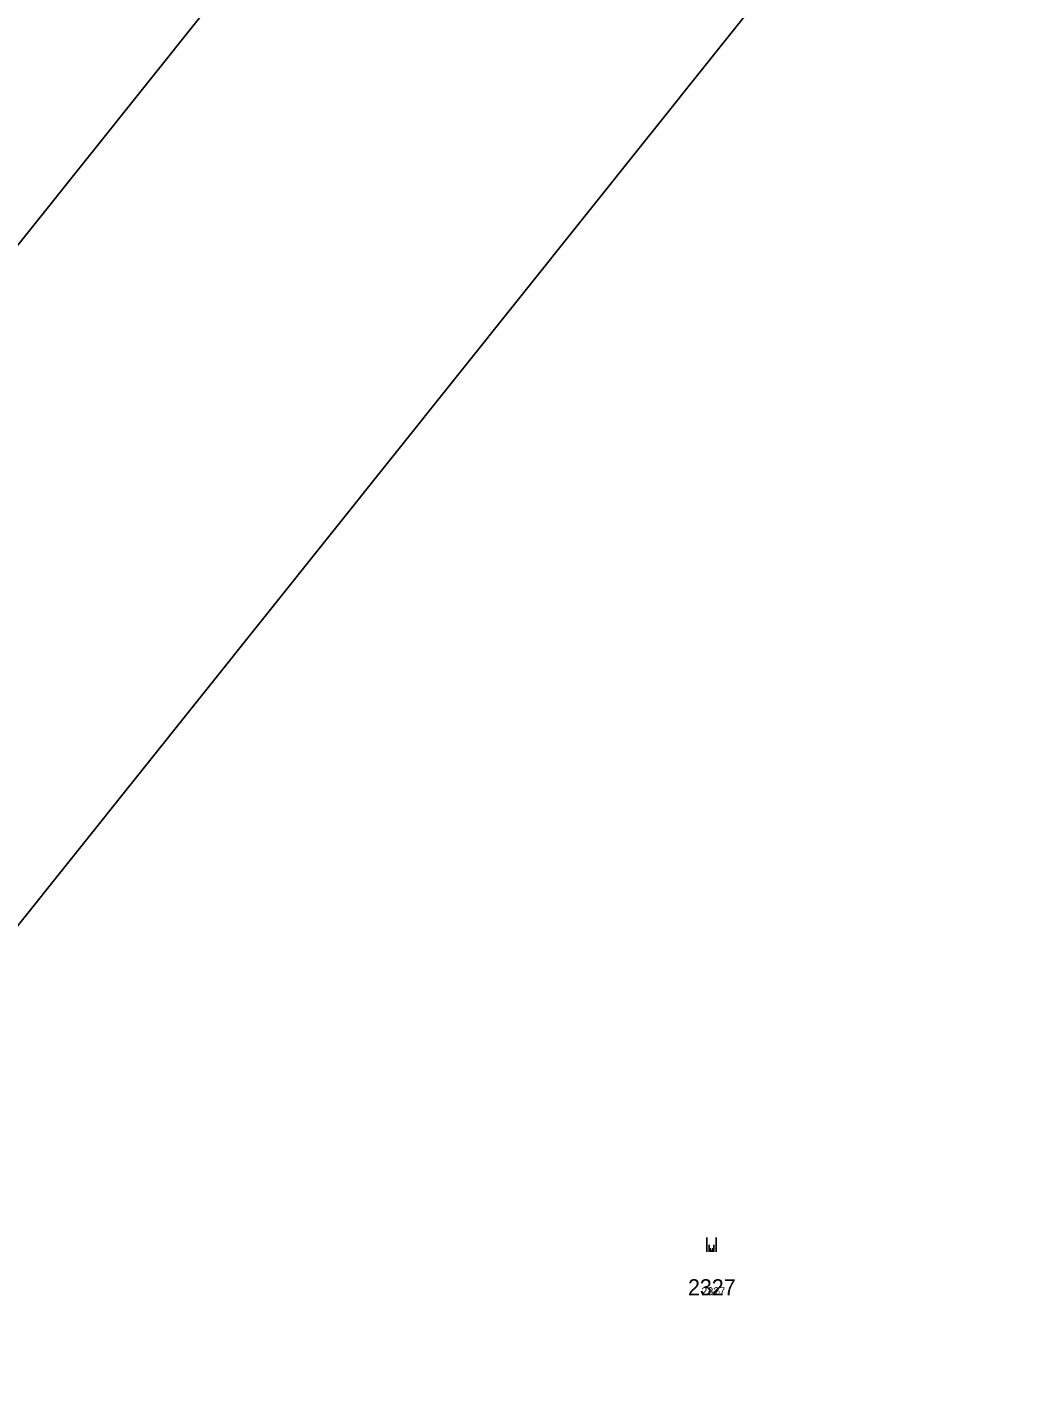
# Model space of a CAD drawing. Extents: x -744652 to -739090, y -980828 to -975855.
# Drawn here: x -743133.3 to -743028.7, y -978620.9 to -978475.5 of the extents above; entities that cross this region are included whole.
import ezdxf

# ---------------------------------------------------------------- set-up
doc = ezdxf.new("R2010")
doc.units = 0
for name, color, linetype in [('KAT_02_hranice parcel', 7, 'Continuous'), ('KAT_03_1000_čísla parcelní', 7, 'Continuous'), ('KAT_03_100_čísla parcelní', 7, 'Continuous'), ('KAT_03_250_čísla parcelní', 7, 'Continuous'), ('KAT_03_500_čísla parcelní', 7, 'Continuous'), ('KAT_05_1000_značky kultur', 7, 'Continuous'), ('KAT_05_100_značky kultur', 7, 'Continuous'), ('KAT_05_250_značky kultur', 7, 'Continuous'), ('KAT_05_500_značky kultur', 7, 'Continuous')]:
    doc.layers.add(name, color=color, linetype=linetype)

msp = doc.modelspace()

# ---------------------------------------------------------------- linework, layer by layer
at = {"layer": 'KAT_02_hranice parcel'}
for points in [[(-743065.01, -978411.82), (-743083.62, -978435.11), (-743195.28, -978574.85), (-743327.49, -978687.68)], [(-743028.68, -978438.64), (-743047.05, -978461.63), (-743169.04, -978614.3), (-743262.9, -978693.89)]]:
    msp.add_lwpolyline(points, dxfattribs=at)
at = {"layer": 'KAT_05_1000_značky kultur'}
for p, q in [((-743061.15, -978605.46), (-743061.15, -978603.96)), ((-743060.15, -978605.46), (-743060.15, -978603.96))]:
    msp.add_line(p, q, dxfattribs=at)
at = {"layer": 'KAT_05_100_značky kultur'}
for p, q in [((-743060.69, -978605.46), (-743060.69, -978605.31)), ((-743060.59, -978605.46), (-743060.59, -978605.31))]:
    msp.add_line(p, q, dxfattribs=at)
at = {"layer": 'KAT_05_250_značky kultur'}
for p, q in [((-743060.77, -978605.46), (-743060.77, -978605.08)), ((-743060.52, -978605.46), (-743060.52, -978605.08))]:
    msp.add_line(p, q, dxfattribs=at)
at = {"layer": 'KAT_05_500_značky kultur'}
for p, q in [((-743060.9, -978605.46), (-743060.9, -978604.71)), ((-743060.4, -978605.46), (-743060.4, -978604.71))]:
    msp.add_line(p, q, dxfattribs=at)

# ---------------------------------------------------------------- texts
at = {"layer": 'KAT_03_1000_čísla parcelní'}
msp.add_text('2327', height=1.7, dxfattribs=at).set_placement((-743063.14, -978610.08))
at = {"layer": 'KAT_03_100_čísla parcelní'}
msp.add_text('2327', height=0.17, dxfattribs=at).set_placement((-743060.58, -978610.08))
at = {"layer": 'KAT_03_250_čísla parcelní'}
msp.add_text('2327', height=0.425, dxfattribs=at).set_placement((-743061.01, -978610.08))
at = {"layer": 'KAT_03_500_čísla parcelní'}
msp.add_text('2327', height=0.85, dxfattribs=at).set_placement((-743061.72, -978610.08))

doc.saveas('drawing.dxf')
